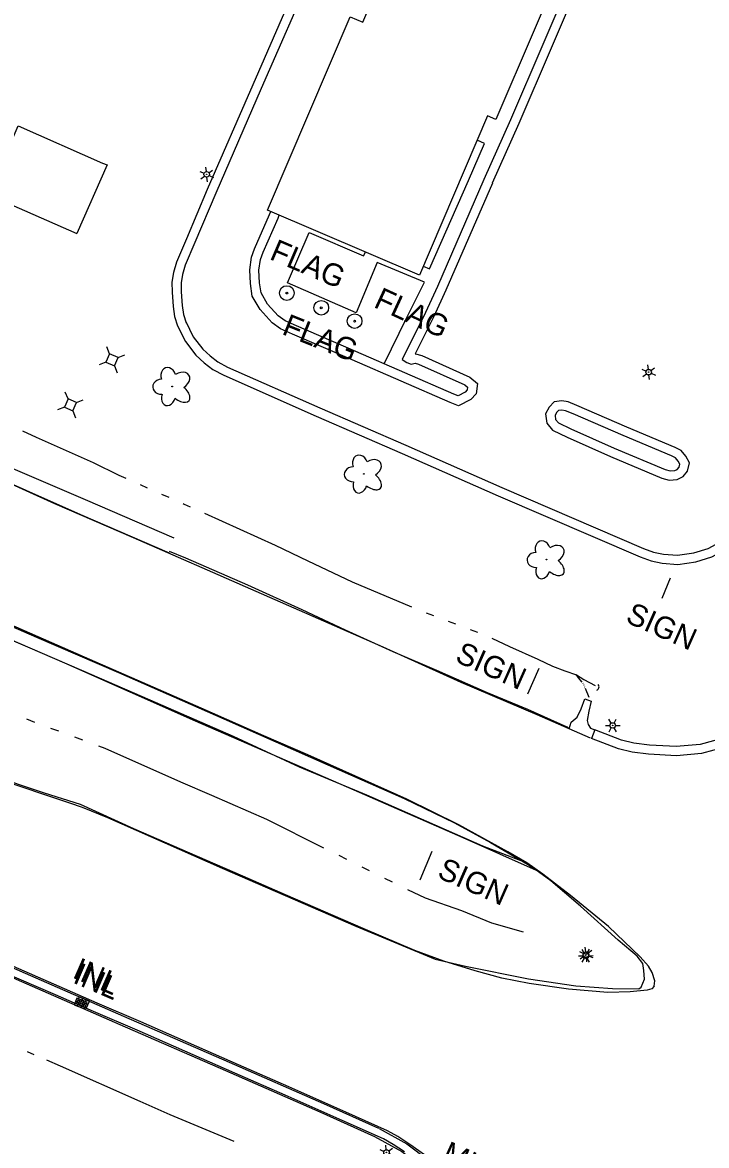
# Model space of a CAD drawing. Extents: x 588843 to 2552415, y 180129 to 269402.
# Drawn here: x 594612.7 to 594799.2, y 185134.3 to 185440.6 of the extents above; entities that cross this region are included whole.
import ezdxf

# ---------------------------------------------------------------- set-up
doc = ezdxf.new("R2010")
doc.units = 0
for name, color, linetype in [('Default', 7, 'Continuous'), ('E_BLD', 7, 'Continuous'), ('E_DRN', 7, 'Continuous'), ('E_DRN_Text', 7, 'Continuous'), ('E_DWY', 7, 'Continuous'), ('E_LAND_Vegetation', 7, 'Continuous'), ('E_LTG', 7, 'Continuous'), ('E_MISCPROP', 7, 'Continuous'), ('E_MISCPROP_Text', 7, 'Continuous'), ('E_PATH_Sidewalk', 7, 'Continuous'), ('E_RDWY', 7, 'Continuous'), ('E_RDWY_AsphConc', 7, 'Continuous'), ('E_RDWY_C_and_G', 7, 'Continuous'), ('E_RDWY_Gravel', 7, 'Continuous'), ('E_SGN', 7, 'Continuous'), ('E_SGN_Text', 7, 'Continuous'), ('E_UTL_AG_Bold', 7, 'Continuous'), ('E_UTL_MH_Text', 7, 'Continuous'), ('E_WTR_P', 7, 'Continuous')]:
    doc.layers.add(name, color=color, linetype=linetype)

# ---------------------------------------------------------------- blocks, each defined once
blk = doc.blocks.new('MHT')
at = {"layer": 'E_UTL_MH_Text'}
blk.add_text('MH', height=12, dxfattribs=at).set_placement((-9.81, -6))
blk = doc.blocks.new('LPOL')
at = {"layer": 'Default'}
for p, q in [((-4, 0), (-1.5, 0)), ((-0.75, 1.3), (-2, 3.46)), ((0.75, 1.3), (2, 3.46)), ((1.5, 0), (4, 0)), ((-2, -3.46), (-0.75, -1.3)), ((2, -3.46), (0.75, -1.3))]:
    blk.add_line(p, q, dxfattribs=at)
for radius in [1.5, 1.5, 1.5, 0.125]:
    blk.add_circle((0, 0), radius, dxfattribs=at)
blk = doc.blocks.new('INLO')
at = {"layer": 'E_DRN'}
for p, q in [((2, -4), (2, 0)), ((4, -4), (4, 0)), ((6, -2), (0, -2))]:
    blk.add_line(p, q, dxfattribs=at)
blk.add_lwpolyline([(0, -4), (6, -4), (6, 0), (0, 0), (0, -4)], close=True, dxfattribs=at)
blk = doc.blocks.new('INLT_52')
at = {"layer": 'E_DRN_Text'}
blk.add_text('INL', height=12, dxfattribs=at).set_placement((-11.03, -6))
blk = doc.blocks.new('SIGN')
at = {"layer": 'Default'}
blk.add_text('SIGN', height=12, dxfattribs=at).set_placement((-18.55, -6))
blk = doc.blocks.new('LPOL_4')
at = {"layer": 'E_LTG'}
for p, q in [((-13.1, 0), (-4.9, 0)), ((-2.5, 4.3), (-6.6, 11.4)), ((2.5, 4.3), (6.6, 11.4)), ((4.9, 0), (13.1, 0)), ((-6.6, -11.4), (-2.5, -4.3)), ((6.6, -11.4), (2.5, -4.3))]:
    blk.add_line(p, q, dxfattribs=at)
for radius in [4.92, 4.92, 4.92, 0.41]:
    blk.add_circle((0, 0), radius, dxfattribs=at)
blk = doc.blocks.new('INLO_3')
at = {"layer": 'E_DRN'}
for p, q in [((6.6, -13.1), (6.6, 0)), ((13.1, -13.1), (13.1, 0)), ((19.7, -6.6), (0, -6.6))]:
    blk.add_line(p, q, dxfattribs=at)
blk.add_lwpolyline([(0, -13.1), (19.7, -13.1), (19.7, 0), (0, 0)], close=True, dxfattribs=at)
blk = doc.blocks.new('INLT_30_1')
at = {"layer": 'E_DRN_Text'}
blk.add_text('INL', height=39.37, dxfattribs=at).set_placement((-36.2, -19.7))
blk = doc.blocks.new('LPOL_5')
at = {"layer": 'E_LTG'}
for p, q in [((-13.1, 0), (-4.9, 0)), ((-2.5, 4.3), (-6.6, 11.4)), ((2.5, 4.3), (6.6, 11.4)), ((4.9, 0), (13.1, 0)), ((-6.6, -11.4), (-2.5, -4.3)), ((6.6, -11.4), (2.5, -4.3))]:
    blk.add_line(p, q, dxfattribs=at)
for radius in [4.92, 4.92, 4.92, 0.41]:
    blk.add_circle((0, 0), radius, dxfattribs=at)
blk = doc.blocks.new('SIGN_4')
at = {"layer": 'E_SGN'}
blk.add_text('SIGN', height=39.37, dxfattribs=at).set_placement((-56.1, -19.7))
blk = doc.blocks.new('CULV2_5')
at = {"layer": 'E_DRN'}
blk.add_arc((65, 48), 80.7, 216.8699, 323.1301, dxfattribs=at)
blk = doc.blocks.new('PED_4')
at = {"layer": 'E_UTL_AG_Bold'}
for p, q in [((-8.2, 8.2), (-17.5, 17.5)), ((8.2, 8.2), (17.5, 17.5)), ((-8.2, -8.2), (-17.5, -17.5)), ((8.2, -8.2), (17.5, -17.5))]:
    blk.add_line(p, q, dxfattribs=at)
blk.add_lwpolyline([(-8.2, -8.2), (8.2, -8.2), (8.2, 8.2), (-8.2, 8.2)], close=True, dxfattribs=at)
blk = doc.blocks.new('DTRE_5')
at = {"layer": 'E_LAND_Vegetation'}
blk.add_circle((-0.6, 0), 0.601, dxfattribs=at)
for centre, major_axis, ratio in [((-6.1, 17.5), (4.5, -16.3), 0.782863), ((13.3, 9), (-17.3, -9.6), 0.691916), ((-19.3, 0.5), (16.2, -0.4), 0.832022), ((-8.2, -17.2), (5.9, 15.9), 0.716896), ((11.6, -12.2), (-16.4, 15), 0.560249)]:
    blk.add_ellipse(centre, major_axis=major_axis, ratio=ratio, start_param=1.570796, end_param=4.712389, dxfattribs=at)

msp = doc.modelspace()

# ---------------------------------------------------------------- linework, layer by layer
at = {"layer": 'E_BLD'}
msp.add_lwpolyline([(594720.92, 185371.72), (594679.49, 185389.41), (594702.02, 185442.16), (594705.46, 185440.69), (594722.35, 185480.22), (594762.62, 185463.02), (594741.76, 185414.17), (594739.47, 185415.15)], close=True, dxfattribs=at)
at = {"layer": 'E_DWY'}
for points in [[(594726.85, 185541.54), (594717.32, 185519.48), (594703.73, 185488.45), (594689.69, 185456.24), (594675.43, 185423.6), (594663.05, 185395.04)], [(594729.14, 185540.55), (594719.61, 185518.48), (594706.02, 185487.45), (594691.98, 185455.24), (594677.73, 185422.6), (594665.34, 185394.04)], [(594838.58, 185509.24), (594809.4, 185521.78), (594795.25, 185527.78), (594782.09, 185497.55), (594774.42, 185480.39), (594763.35, 185455.3), (594745.71, 185414.07), (594738.5, 185397.81)], [(594837.59, 185506.94), (594808.42, 185519.48), (594796.55, 185524.51), (594784.38, 185496.54), (594776.7, 185479.38), (594765.64, 185454.31), (594748, 185413.07), (594740.78, 185396.79)], [(594740.79, 185396.81), (594728.14, 185367.64), (594724.83, 185360.42), (594719.71, 185350.21), (594719.87, 185350.24), (594721.55, 185349.76), (594734.65, 185343.89), (594736.72, 185342.15), (594736.33, 185339.32), (594734.9, 185337.77), (594731.6, 185336.07), (594729.3, 185336.93), (594702.57, 185348.58)], [(594738.5, 185397.81), (594725.86, 185368.66), (594722.58, 185361.51), (594716.15, 185348.7), (594717.46, 185347.92), (594718.67, 185347.47), (594719.75, 185347.68), (594720.69, 185347.4), (594733.31, 185341.75), (594734.05, 185341.12), (594733.96, 185340.43), (594733.36, 185339.79), (594731.44, 185338.8), (594730.24, 185339.25), (594703.56, 185350.87)], [(594663.05, 185395.04), (594657.39, 185381.6), (594654.68, 185375.25), (594653.88, 185372.47), (594653.41, 185369.8), (594653.44, 185367.08), (594653.73, 185363.18), (594654.15, 185360.45), (594654.93, 185357.92)], [(594665.35, 185394.07), (594659.7, 185380.62), (594657.04, 185374.41), (594656.32, 185371.91), (594655.92, 185369.59), (594655.94, 185367.18), (594656.21, 185363.47), (594656.59, 185361.02), (594657.32, 185358.66)], [(594702.57, 185348.58), (594686.33, 185355.58), (594683, 185357.09), (594680.72, 185358.75), (594677.49, 185362.31), (594675.33, 185366.02), (594674.81, 185369.41), (594674.64, 185373.2), (594675.15, 185376.61), (594675.92, 185378.89), (594680.03, 185388.22), (594680.36, 185389.04)], [(594703.56, 185350.87), (594687.34, 185357.87), (594684.26, 185359.26), (594682.39, 185360.62), (594679.51, 185363.8), (594677.73, 185366.87), (594677.3, 185369.65), (594677.15, 185373.07), (594677.59, 185376.02), (594678.25, 185377.98), (594682.34, 185387.26), (594682.66, 185388.06)], [(594657.17, 185359.04), (594659.23, 185354.92), (594661.8, 185351.56), (594663.8, 185349.72), (594665.92, 185348.04), (594668.6, 185346.64), (594693.74, 185335.55)], [(594654.93, 185357.92), (594657.1, 185353.59), (594659.95, 185349.86), (594662.18, 185347.82), (594664.55, 185345.94), (594667.52, 185344.39), (594692.73, 185333.26)], [(594777.48, 185330.26), (594763.83, 185336.17), (594761.47, 185337.13), (594759.76, 185337.46), (594757.6, 185337.17), (594756.26, 185335.71), (594755.29, 185333.91), (594755.65, 185331.38), (594757.15, 185329.4), (594761.15, 185327.48), (594772.96, 185322.25)], [(594693.73, 185335.55), (594717.19, 185325.32), (594743.4, 185313.81)], [(594776.48, 185327.97), (594762.86, 185333.86), (594760.75, 185334.72), (594759.69, 185334.92), (594758.83, 185334.81), (594758.31, 185334.24), (594757.88, 185333.44), (594758.04, 185332.38), (594758.78, 185331.4), (594762.2, 185329.75), (594773.97, 185324.54)], [(594692.73, 185333.26), (594716.19, 185323.03), (594742.4, 185311.52)], [(594773, 185322.23), (594787.04, 185316.36), (594789.03, 185315.79), (594791.22, 185315.96), (594792.82, 185316.75), (594794, 185318.28), (594794.5, 185320.51), (594793.59, 185322.33), (594792.3, 185323.91), (594790.66, 185324.69), (594777.46, 185330.27)], [(594773.97, 185324.54), (594787.87, 185318.72), (594789.28, 185318.31), (594790.54, 185318.41), (594791.2, 185318.74), (594791.69, 185319.37), (594791.87, 185320.19), (594791.48, 185320.96), (594790.72, 185321.9), (594789.64, 185322.41), (594776.48, 185327.97)], [(594742.4, 185311.52), (594781.07, 185294.83), (594784.08, 185293.77), (594787.1, 185293.11), (594791.33, 185292.8), (594796.24, 185293.5), (594800.64, 185294.85), (594804.2, 185296.74), (594807.63, 185299.27), (594810.61, 185302.33), (594812.91, 185305.79), (594819.1, 185320.07)], [(594743.39, 185313.81), (594781.98, 185297.16), (594784.77, 185296.18), (594787.46, 185295.59), (594791.24, 185295.31), (594795.7, 185295.95), (594799.68, 185297.17), (594802.86, 185298.86), (594805.98, 185301.16), (594808.66, 185303.91), (594810.7, 185306.99), (594816.81, 185321.07)]]:
    msp.add_lwpolyline(points, dxfattribs=at)
at = {"layer": 'E_MISCPROP'}
for centre, radius in [((594684.74, 185366.83), 2), ((594684.74, 185366.83), 0.25), ((594694.14, 185362.81), 2), ((594694.14, 185362.81), 0.25), ((594703.24, 185359.18), 2), ((594703.24, 185359.18), 0.25)]:
    msp.add_circle(centre, radius, dxfattribs=at)
at = {"layer": 'E_PATH_Sidewalk'}
for points in [[(594721.96, 185374.15), (594723.64, 185373.41), (594734.26, 185397.57), (594738.65, 185407.65), (594736.64, 185408.53)], [(594711.31, 185347.5), (594717.38, 185359.95), (594722.3, 185369.78), (594709.4, 185375.18), (594703.66, 185361.47), (594684.93, 185369.64), (594690.87, 185383.39), (594705.69, 185376.95), (594706.18, 185378.01)]]:
    msp.add_lwpolyline(points, dxfattribs=at)
at = {"layer": 'E_RDWY'}
for points in [[(594296.88, 185411.87), (594325.62, 185399.4), (594349.95, 185388.9), (594374.77, 185378.12), (594397.2, 185368.32), (594422.63, 185357.35), (594444.66, 185347.72), (594469.29, 185337.04), (594493.12, 185326.74), (594515.85, 185316.9), (594539.82, 185306.36), (594564.27, 185295.73), (594590.16, 185284.43), (594616.48, 185273), (594638.84, 185263.28), (594667.59, 185250.7), (594695.94, 185238.13), (594716.7, 185228.91), (594730.42, 185222.27), (594740.31, 185216.94), (594750.4, 185211.08), (594752.94, 185209.36)], [(594384.9, 185413.36), (594391.73, 185409.66), (594405.93, 185403.45), (594421.24, 185396.86), (594441.64, 185388), (594473.72, 185373.96), (594499.14, 185363.15), (594519.99, 185354.07), (594541.44, 185344.6), (594561.26, 185335.85), (594580.09, 185327.6), (594600.85, 185318.74), (594621.43, 185309.42), (594642.83, 185300.12), (594664.5, 185290.7), (594686.69, 185280.92), (594710.89, 185270.31), (594732.2, 185260.72), (594752.9, 185251.83), (594767.48, 185245.51)], [(594674.14, 185287.12), (594657.16, 185294.49), (594652.75, 185296.35)], [(594784.94, 185177.8), (594785.08, 185179.2), (594784.4, 185181.48), (594783.37, 185183.2), (594781.11, 185185.75), (594772.43, 185194.02), (594762.07, 185202.45), (594754.55, 185208.28), (594750.23, 185211.44), (594745, 185214.44), (594731.64, 185221.77), (594717.43, 185228.78), (594703.51, 185235.06), (594690.51, 185240.87), (594678.43, 185246.04), (594661.35, 185253.58), (594645.43, 185260.62), (594631.02, 185266.85), (594609.49, 185276.28), (594587.28, 185285.68)], [(594761.49, 185248.25), (594761.16, 185248.39), (594750.43, 185253.21), (594739.49, 185257.74), (594725.63, 185263.84), (594713.78, 185268.94), (594700.73, 185274.84), (594688.9, 185280.4), (594674.14, 185287.12)], [(594761.76, 185247.99), (594762.31, 185249.76), (594763.9, 185251.11), (594764.96, 185253.42), (594766.03, 185256.12), (594767.77, 185255.53), (594767.09, 185252.81), (594766.65, 185250.23), (594766.94, 185249.14), (594767.57, 185248.16), (594768.73, 185247.66), (594767.84, 185245.33)], [(594784.94, 185177.8), (594784.28, 185177.01), (594782.99, 185176.71), (594778.4, 185176.21), (594772.3, 185176.03), (594761.57, 185176.9), (594750.83, 185178.46), (594743.38, 185179.97), (594736.09, 185181.95), (594727.57, 185184.54), (594719.69, 185187.48), (594705.57, 185193.45), (594684.35, 185202.71), (594672.74, 185207.8), (594660.39, 185213.15), (594643.06, 185220.72), (594628.44, 185227.31), (594618.69, 185230.45), (594603.7, 185235.43)], [(594605.57, 185234.41), (594625.49, 185227.79), (594628.94, 185226.6), (594635.82, 185223.81), (594667.07, 185209.95), (594703.59, 185194.08), (594725.19, 185185.13), (594733.44, 185183.18), (594750.6, 185179.8), (594763.55, 185177.84), (594773.58, 185177.12), (594780.72, 185177.02), (594781.36, 185177.45), (594782.29, 185179.64), (594782.06, 185182.06), (594781.79, 185183.98), (594780.31, 185185.94), (594775.1, 185190.3), (594764.86, 185199.58), (594756.71, 185206.52), (594752.76, 185209.38)]]:
    msp.add_lwpolyline(points, dxfattribs=at)
at = {"layer": 'E_RDWY_AsphConc'}
for points in [[(594603.36, 185393.63), (594603.97, 185394.95), (594611.51, 185412.46), (594634.48, 185402.3), (594635.77, 185401.79), (594627.5, 185383.04)], [(594603.36, 185393.63), (594627.5, 185383.04)], [(594583.64, 185326.33), (594628.44, 185306.4), (594652.62, 185295.93)]]:
    msp.add_lwpolyline(points, dxfattribs=at)
at = {"layer": 'E_RDWY_C_and_G'}
for points in [[(594716.87, 185132.54), (594713.76, 185134.58), (594711.06, 185136.08), (594699.81, 185141.15), (594684.3, 185148.01), (594670.6, 185154.04), (594659.19, 185159.04), (594643.95, 185165.72), (594631.99, 185170.86), (594621.66, 185175.35), (594607.74, 185181.43), (594595.58, 185186.75), (594580.7, 185193.26), (594568.95, 185198.46), (594557.86, 185203.38), (594546.4, 185208.35), (594528.96, 185215.94), (594516.25, 185221.38), (594500.75, 185228.22), (594485.74, 185234.83), (594471.59, 185241.01), (594457.31, 185247.21), (594442.22, 185253.67), (594428.73, 185259.27)], [(594816.47, 185251.82), (594809.69, 185247.75), (594803.76, 185245.44), (594797.41, 185243.7), (594790.94, 185243.14), (594783.6, 185243.52), (594779.39, 185244.04), (594775.97, 185244.9), (594768.73, 185247.66)], [(594817.75, 185249.68), (594810.8, 185245.5), (594804.54, 185243.06), (594797.85, 185241.23), (594790.99, 185240.63), (594783.38, 185241.03), (594778.93, 185241.58), (594775.21, 185242.52), (594767.84, 185245.33)], [(594542.37, 185212.41), (594579.07, 185196.4), (594613.4, 185181.3), (594640.21, 185169.61)], [(594541.37, 185210.11), (594578.07, 185194.11), (594612.4, 185179.01), (594639.21, 185167.32)], [(594722.24, 185131.71), (594718.29, 185134.6), (594715.05, 185136.72), (594712.19, 185138.31), (594700.83, 185143.43), (594685.31, 185150.3), (594671.6, 185156.33), (594660.2, 185161.33), (594644.94, 185168.01), (594632.99, 185173.16), (594622.66, 185177.64), (594608.75, 185183.72)], [(594640.21, 185169.61), (594669.06, 185157), (594694.75, 185145.75), (594709.7, 185139.06)], [(594639.21, 185167.32), (594668.06, 185154.71), (594693.74, 185143.46), (594708.68, 185136.77)], [(594709.89, 185138.96), (594717.46, 185134.78), (594723.39, 185130.33), (594729.01, 185124.89), (594733.83, 185118.72), (594738.81, 185110.41), (594742.65, 185101.37)], [(594708.68, 185136.77), (594716.1, 185132.68), (594721.76, 185128.42), (594727.15, 185123.21), (594731.77, 185117.3), (594736.58, 185109.27), (594740.35, 185100.4)]]:
    msp.add_lwpolyline(points, dxfattribs=at)
at = {"layer": 'E_RDWY_Gravel'}
for points in [[(594294.77, 185410.38), (594323, 185398.2), (594352.64, 185385.11), (594378.47, 185373.42), (594417.21, 185356.7), (594461.03, 185337.4), (594502.73, 185319.22), (594545.58, 185300.1), (594582.07, 185284.13), (594624.08, 185265.97), (594659.78, 185250.12), (594703.03, 185231.29), (594732.78, 185218.27), (594752.76, 185209.38), (594752.81, 185209.45)], [(594541.17, 185349.71), (594585.08, 185329.59), (594629.77, 185310.49), (594653.95, 185300.02)], [(594578.41, 185285.82), (594595.95, 185278.05), (594614.06, 185270.36), (594628.73, 185263.95), (594645.28, 185256.82), (594670.13, 185245.95), (594688.1, 185237.61), (594706.5, 185229.93), (594722.84, 185222.76), (594738.06, 185216.05), (594750.23, 185211.44)]]:
    msp.add_lwpolyline(points, dxfattribs=at)
at = {"layer": 'E_SGN'}
for p, q in [((594789.23, 185289.01), (594787.04, 185283.49)), ((594753.43, 185264.44), (594750.4, 185257.43))]:
    msp.add_line(p, q, dxfattribs=at)
msp.add_lwpolyline([(594724.24, 185214.48), (594720.99, 185206.68)], dxfattribs=at)
at = {"layer": 'E_WTR_P'}
for points in [[(594612.66, 185329.26), (594616.39, 185327.54), (594631.96, 185320.58), (594638.91, 185317.19), (594640.82, 185316.34)], [(594644.73, 185314.6), (594646.68, 185313.74)], [(594650.59, 185312), (594652.55, 185311.13)], [(594656.45, 185309.4), (594656.72, 185309.28), (594658.4, 185308.52)], [(594662.3, 185306.76), (594681.6, 185298.05), (594690.46, 185293.81)], [(594690.46, 185293.81), (594702.52, 185288.05), (594718.76, 185281.2)], [(594722.74, 185279.63), (594724.74, 185278.87)], [(594728.73, 185277.35), (594730.73, 185276.59)], [(594734.72, 185275.06), (594736.72, 185274.3)], [(594740.67, 185272.66), (594745.45, 185270.44), (594753.17, 185266.93), (594757.16, 185265.08), (594760.51, 185263.82), (594763.7, 185262.71), (594765.74, 185261.42), (594768.78, 185259.75)], [(594765.24, 185260.7), (594764.26, 185261.85), (594763.61, 185262.74)], [(594765.59, 185260.28), (594765.47, 185260.42)], [(594765.8, 185259.79), (594765.74, 185259.95)], [(594766.01, 185259.28), (594765.94, 185259.45)], [(594767.15, 185256.51), (594766.15, 185258.94)], [(594613.76, 185250.65), (594615.93, 185249.81)], [(594620.28, 185248.17), (594622.46, 185247.37)], [(594626.82, 185245.76), (594629, 185244.95)], [(594633.37, 185243.35), (594635.09, 185242.71), (594655.71, 185233.53), (594664.24, 185229.83)], [(594664.24, 185229.83), (594679.21, 185223.33), (594694.75, 185215.53)], [(594698.91, 185213.45), (594700.99, 185212.42)], [(594705.16, 185210.35), (594707.24, 185209.32)], [(594711.41, 185207.25), (594713.49, 185206.22)], [(594717.66, 185204.17), (594722.51, 185201.82), (594732.38, 185198.38), (594740.53, 185195.03), (594749.23, 185192.54)], [(594615.8, 185159.05), (594614.04, 185159.8)], [(594644.79, 185146.3), (594623.06, 185155.95), (594619.33, 185157.54)], [(594670.4, 185135.42), (594652.95, 185142.68), (594644.79, 185146.3)]]:
    msp.add_lwpolyline(points, dxfattribs=at)

# ---------------------------------------------------------------- block references
at = {"layer": 'E_DRN'}
for name, p, xscale, yscale, rotation in [('CULV2_5', (594769.23, 185258.49), 0.012196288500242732, 0.012196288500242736, 74.03022120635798), ('INLO_3', (594628.15, 185174.87), 0.1524003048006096, 0.15240030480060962, -23.562837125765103), ('INLO', (594627.49, 185174.49), 0.5, 0.5, -21.379410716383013)]:
    msp.add_blockref(name, p, dxfattribs=dict(at, xscale=xscale, yscale=yscale, rotation=rotation))
at = {"layer": 'E_DRN_Text'}
for name, p, xscale, yscale, rotation in [('INLT_30_1', (594632.23, 185180.74), 0.1524003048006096, 0.15240030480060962, -23.562837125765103), ('INLT_52', (594632.37, 185179.38), 0.49999999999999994, 0.49999999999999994, -23.250228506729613)]:
    msp.add_blockref(name, p, dxfattribs=dict(at, xscale=xscale, yscale=yscale, rotation=rotation))
at = {"layer": 'E_LAND_Vegetation', "xscale": 0.15240030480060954, "yscale": 0.15240030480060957, "rotation": 3.4338469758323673}
for p in [(594653.57, 185341.36), (594705.82, 185317.5), (594755.65, 185294.12)]:
    msp.add_blockref('DTRE_5', p, dxfattribs=at)
at = {"layer": 'E_LTG'}
for name, p, xscale, yscale, rotation in [('LPOL_5', (594662.88, 185399.2), 0.1524003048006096, 0.1524003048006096, -23.954644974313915), ('LPOL_5', (594783.41, 185345.25), 0.1524003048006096, 0.1524003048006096, -23.954644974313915), ('LPOL_5', (594773.6, 185248.88), 0.15240030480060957, 0.15240030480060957, 0.8014450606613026), ('LPOL', (594766.34, 185186.37), 0.5, 0.5, -23.807133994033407), ('LPOL_4', (594766.27, 185186.06), 0.15240030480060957, 0.15240030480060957, 0.8014450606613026), ('LPOL', (594711.92, 185132.39), 0.5, 0.5, -24.25797329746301)]:
    msp.add_blockref(name, p, dxfattribs=dict(at, xscale=xscale, yscale=yscale, rotation=rotation))
at = {"layer": 'E_SGN_Text'}
for name, p, xscale, yscale, rotation in [('SIGN_4', (594785.85, 185276.46), 0.1524003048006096, 0.1524003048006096, -23.954644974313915), ('SIGN_4', (594739.35, 185265.71), 0.1524003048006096, 0.1524003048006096, -23.954644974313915), ('SIGN', (594735.16, 185206.52), 0.5, 0.5, -23.807133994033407)]:
    msp.add_blockref(name, p, dxfattribs=dict(at, xscale=xscale, yscale=yscale, rotation=rotation))
at = {"layer": 'E_UTL_AG_Bold', "xscale": 0.15240030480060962, "yscale": 0.1524003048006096, "rotation": -23.509223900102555}
for p in [(594637.07, 185348.62), (594625.72, 185336.31)]:
    msp.add_blockref('PED_4', p, dxfattribs=at)
at = {"layer": 'E_UTL_MH_Text', "xscale": 0.5, "yscale": 0.5, "rotation": -24.25797329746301}
msp.add_blockref('MHT', (594732.33, 185130.86), dxfattribs=at)

# ---------------------------------------------------------------- texts
at = {"layer": 'E_MISCPROP_Text'}
for rotation, p in [(336.8368, (594679.74, 185376.18)), (335.3439, (594708.14, 185363.1)), (338.2623, (594683.12, 185355.7))]:
    msp.add_text('FLAG', height=6, rotation=rotation, dxfattribs=at).set_placement(p)

doc.saveas('drawing.dxf')
